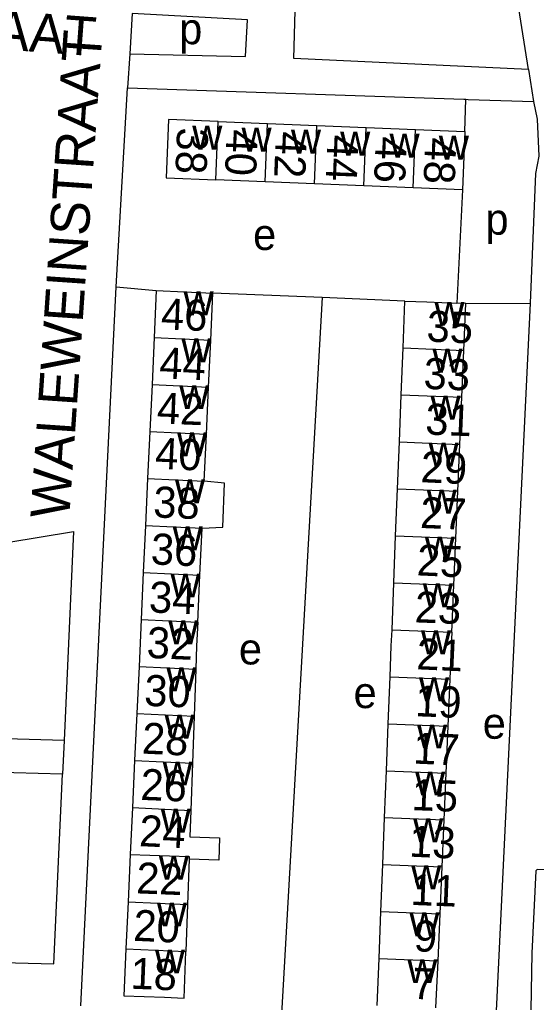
# Model space of a CAD drawing. Extents: x 159675 to 162108, y 386471 to 388472.
# Drawn here: x 160779.5 to 160845.9, y 386954.2 to 387080.5 of the extents above; entities that cross this region are included whole.
import ezdxf

# ---------------------------------------------------------------- set-up
doc = ezdxf.new("R2010")
doc.units = 0
for name, color, linetype in [('BLT_Basislijn', 7, 'Continuous'), ('BLT_Bebouwing', 7, 'Continuous'), ('BLT_Centroide', 7, 'Continuous'), ('BLT_Huisnummer', 7, 'Continuous'), ('BLT_Huisnummer_ tussenligend', 7, 'Continuous'), ('BLT_Onderverdeling_panden', 7, 'Continuous'), ('BLT_Straatnaam', 7, 'Continuous')]:
    doc.layers.add(name, color=color, linetype=linetype)

msp = doc.modelspace()

# ---------------------------------------------------------------- linework, layer by layer
at = {"layer": 'BLT_Basislijn'}
for p, q in [((160793.9, 387081.23), (160793.62, 387076.05)), ((160793.62, 387076.05), (160793.32, 387071.69)), ((160844.85, 387074.04), (160845.51, 387069.92)), ((160791.86, 387046.11), (160793.32, 387071.69)), ((160793.32, 387071.69), (160836.55, 387070.22)), ((160836.55, 387070.22), (160836.82, 387070.22)), ((160836.67, 387066.1), (160836.82, 387070.22)), ((160836.37, 387058.61), (160835.66, 387044.02)), ((160787.31, 386953.76), (160791.86, 387046.11)), ((160791.86, 387046.11), (160797.02, 387045.67)), ((160818.35, 387044.74), (160804.3, 387045.33)), ((160818.35, 387044.74), (160813.1, 386952.69)), ((160828.98, 387044.3), (160818.35, 387044.74)), ((160836.79, 387043.97), (160845.06, 387044.05)), ((160845.06, 387044.05), (160839.85, 386934.69)), ((160785.2, 386987.85), (160784.97, 386983.53))]:
    msp.add_line(p, q, dxfattribs=at)
for points in [[(160844.85, 387074.04), (160814.71, 387075.45), (160815.38, 387100), (160815.63, 387108.74)], [(160844.85, 387074.04), (160840.74, 387100), (160839.47, 387108.01)], [(160793.62, 387076.05), (160808.47, 387075.74), (160808.76, 387080.42), (160793.9, 387081.23)], [(160836.82, 387070.22), (160837.1, 387070.21), (160845.51, 387069.92)], [(160845.51, 387069.92), (160845.99, 387067.68), (160846.21, 387062.9)], [(160846.21, 387062.9), (160845.78, 387060.7), (160845.06, 387044.05)], [(160735.6, 386960.39), (160728.94, 387001.16), (160729.22, 387003.9), (160731.01, 387005.56), (160786.36, 387014.7), (160785.2, 386987.85)], [(160785.2, 386987.85), (160776.15, 386988.09), (160775.89, 386988.32), (160775.92, 386995.02), (160753.34, 386995.77), (160751.93, 386960.01)], [(160784.97, 386983.53), (160756.75, 386984.3), (160755.83, 386959.87)], [(160755.83, 386959.87), (160783.87, 386959.13), (160784.97, 386983.53)], [(160860.44, 386970.92), (160845.97, 386971.28), (160845.81, 386971.07), (160845.29, 386960.51), (160845.09, 386948.32), (160864.77, 386916.45), (160865.08, 386915.53)]]:
    msp.add_lwpolyline(points, dxfattribs=at)
at = {"layer": 'BLT_Bebouwing'}
for p, q in [((160804.96, 387067.37), (160811.3, 387067.11)), ((160811.3, 387067.11), (160817.64, 387066.86)), ((160817.64, 387066.86), (160823.99, 387066.61)), ((160823.99, 387066.61), (160830.33, 387066.35)), ((160830.33, 387066.35), (160836.67, 387066.1)), ((160836.67, 387066.1), (160836.37, 387058.61)), ((160811, 387059.62), (160804.66, 387059.87)), ((160817.34, 387059.37), (160811, 387059.62)), ((160823.69, 387059.11), (160817.34, 387059.37)), ((160830.03, 387058.86), (160823.69, 387059.11)), ((160836.37, 387058.61), (160830.03, 387058.86)), ((160797.02, 387045.67), (160796.74, 387039.63)), ((160797.02, 387045.67), (160804.3, 387045.33)), ((160804.02, 387039.29), (160804.3, 387045.33)), ((160828.74, 387038.27), (160828.98, 387044.3)), ((160836.79, 387043.97), (160835.66, 387044.02)), ((160836.54, 387037.96), (160836.79, 387043.97)), ((160796.74, 387039.63), (160796.47, 387033.59)), ((160803.74, 387033.25), (160804.02, 387039.29)), ((160828.51, 387032.23), (160828.74, 387038.27)), ((160836.28, 387031.93), (160836.54, 387037.96)), ((160796.47, 387033.59), (160796.19, 387027.55)), ((160803.46, 387027.21), (160803.74, 387033.25)), ((160828.27, 387026.2), (160828.51, 387032.23)), ((160836.03, 387025.89), (160836.28, 387031.93)), ((160796.19, 387027.55), (160795.91, 387021.5)), ((160803.18, 387021.17), (160803.46, 387027.21)), ((160828.03, 387020.16), (160828.27, 387026.2)), ((160835.77, 387019.86), (160836.03, 387025.89)), ((160795.91, 387021.5), (160795.63, 387015.46)), ((160827.79, 387014.13), (160828.03, 387020.16)), ((160835.52, 387013.83), (160835.77, 387019.86)), ((160795.63, 387015.46), (160795.35, 387009.42)), ((160802.62, 387009.08), (160802.9, 387015.13)), ((160827.55, 387008.1), (160827.79, 387014.13)), ((160835.26, 387007.79), (160835.52, 387013.83)), ((160795.35, 387009.42), (160795.07, 387003.38)), ((160802.34, 387003.04), (160802.62, 387009.08)), ((160827.32, 387002.06), (160827.55, 387008.1)), ((160835.01, 387001.76), (160835.26, 387007.79)), ((160795.07, 387003.38), (160794.8, 386997.34)), ((160794.8, 386997.34), (160794.52, 386991.29)), ((160802.1, 386997), (160801.88, 386990.95)), ((160826.84, 386989.99), (160827.08, 386996.03)), ((160834.75, 386995.73), (160834.49, 386989.69)), ((160794.52, 386991.29), (160794.24, 386985.25)), ((160801.88, 386990.95), (160801.67, 386984.91)), ((160826.6, 386983.96), (160826.84, 386989.99)), ((160834.49, 386989.69), (160834.23, 386983.66)), ((160794.24, 386985.25), (160793.96, 386979.21)), ((160801.67, 386984.91), (160801.46, 386978.86)), ((160826.36, 386977.93), (160826.6, 386983.96)), ((160834.23, 386983.66), (160833.97, 386977.63)), ((160793.96, 386979.21), (160793.68, 386973.17)), ((160826.12, 386971.89), (160826.36, 386977.93)), ((160833.97, 386977.63), (160833.71, 386971.59)), ((160793.68, 386973.17), (160793.4, 386967.12)), ((160801.23, 386972.61), (160801.03, 386966.77)), ((160825.89, 386965.86), (160826.12, 386971.89)), ((160833.71, 386971.59), (160833.45, 386965.56)), ((160793.4, 386967.12), (160793.12, 386961.08)), ((160801.03, 386966.77), (160800.82, 386960.73)), ((160825.65, 386959.82), (160825.89, 386965.86)), ((160833.45, 386965.56), (160833.19, 386959.53)), ((160825.41, 386953.79), (160825.65, 386959.82)), ((160833.19, 386959.53), (160832.93, 386953.49))]:
    msp.add_line(p, q, dxfattribs=at)
for points in [[(160804.96, 387067.37), (160798.61, 387067.62), (160798.31, 387060.12), (160804.66, 387059.87)], [(160828.98, 387044.3), (160831.79, 387044.18), (160835.66, 387044.02)], [(160802.9, 387015.13), (160805.58, 387015.25), (160805.81, 387020.91), (160803.18, 387021.17)], [(160802.34, 387003.04), (160802.2, 387000), (160802.1, 386997)], [(160827.08, 386996.03), (160827.23, 387000), (160827.32, 387002.06)], [(160835.01, 387001.76), (160834.93, 387000), (160834.75, 386995.73)], [(160801.46, 386978.86), (160801.34, 386975.48), (160805.16, 386975.35), (160805.06, 386972.47), (160801.23, 386972.61)], [(160793.12, 386961.08), (160792.84, 386955.04), (160798.06, 386954.84), (160800.6, 386954.73), (160800.82, 386960.73)]]:
    msp.add_lwpolyline(points, dxfattribs=at)
at = {"layer": 'BLT_Onderverdeling_panden'}
for p, q in [((160804.66, 387059.87), (160804.96, 387067.37)), ((160811, 387059.62), (160811.3, 387067.11)), ((160817.34, 387059.37), (160817.64, 387066.86)), ((160823.69, 387059.11), (160823.99, 387066.61)), ((160830.03, 387058.86), (160830.33, 387066.35)), ((160796.74, 387039.63), (160804.02, 387039.29)), ((160828.74, 387038.27), (160836.54, 387037.96)), ((160796.47, 387033.59), (160803.74, 387033.25)), ((160828.51, 387032.23), (160836.28, 387031.93)), ((160796.19, 387027.55), (160803.46, 387027.21)), ((160828.27, 387026.2), (160836.03, 387025.89)), ((160795.91, 387021.5), (160803.18, 387021.17)), ((160828.03, 387020.16), (160835.77, 387019.86)), ((160795.63, 387015.46), (160802.9, 387015.13)), ((160827.79, 387014.13), (160835.52, 387013.83)), ((160795.35, 387009.42), (160802.62, 387009.08)), ((160827.55, 387008.1), (160835.26, 387007.79)), ((160795.07, 387003.38), (160802.34, 387003.04)), ((160827.32, 387002.06), (160835.01, 387001.76)), ((160794.8, 386997.34), (160802.1, 386997)), ((160827.08, 386996.03), (160834.75, 386995.73)), ((160794.52, 386991.29), (160801.88, 386990.95)), ((160826.84, 386989.99), (160834.49, 386989.69)), ((160794.24, 386985.25), (160801.67, 386984.91)), ((160826.6, 386983.96), (160834.23, 386983.66)), ((160793.96, 386979.21), (160801.46, 386978.86)), ((160826.36, 386977.93), (160833.97, 386977.63)), ((160826.12, 386971.89), (160833.71, 386971.59)), ((160793.4, 386967.12), (160801.03, 386966.77)), ((160825.89, 386965.86), (160833.45, 386965.56)), ((160793.12, 386961.08), (160800.82, 386960.73)), ((160825.65, 386959.82), (160833.19, 386959.53))]:
    msp.add_line(p, q, dxfattribs=at)
msp.add_lwpolyline([(160793.68, 386973.17), (160801.25, 386972.94), (160801.23, 386972.61)], dxfattribs=at)

# ---------------------------------------------------------------- texts
at = {"layer": 'BLT_Centroide'}
for s, p in [('p', (160799.96, 387077.3)), ('w', (160801.64, 387063.75)), ('w', (160807.98, 387063.5)), ('w', (160814.33, 387063.25)), ('w', (160820.66, 387062.98)), ('w', (160827, 387062.73)), ('w', (160833.34, 387062.47)), ('p', (160839.33, 387052.83)), ('e', (160809.46, 387050.86)), ('w', (160800.52, 387042.47)), ('w', (160832.77, 387041.12)), ('w', (160800.24, 387036.44)), ('w', (160832.52, 387035.09)), ('w', (160799.96, 387030.41)), ('w', (160832.27, 387029.06)), ('w', (160799.69, 387024.34)), ('w', (160832.02, 387023.03)), ('w', (160799.41, 387018.31)), ('w', (160831.78, 387017)), ('w', (160799.12, 387012.28)), ('w', (160831.53, 387010.97)), ('w', (160798.84, 387006.22)), ('w', (160831.28, 387004.94)), ('w', (160798.56, 387000.19)), ('w', (160831.04, 386998.91)), ('e', (160807.64, 386997.61)), ('w', (160798.32, 386994.16)), ('e', (160822.38, 386992)), ('w', (160830.79, 386992.88)), ('e', (160838.98, 386988.06)), ('w', (160798.08, 386988.09)), ('w', (160830.54, 386986.81)), ('w', (160797.83, 386982.06)), ('w', (160830.29, 386980.78)), ('w', (160797.59, 386976)), ('w', (160830.04, 386974.75)), ('w', (160797.34, 386969.97)), ('w', (160829.79, 386968.72)), ('w', (160797.09, 386963.94)), ('w', (160829.55, 386962.69)), ('w', (160796.84, 386957.91)), ('w', (160829.29, 386956.66))]:
    msp.add_text(s, height=4, dxfattribs=at).set_placement(p)
at = {"layer": 'BLT_Huisnummer'}
for s, rotation, p in [('38', 267.7155, (160799.71, 387066.64)), ('42', 267.7155, (160812.4, 387066.14)), ('48', 267.7155, (160831.61, 387065.36)), ('46', 357.7256, (160797.57, 387040.67)), ('35', 357.426, (160831.71, 387039.11)), ('42', 357.7256, (160797.05, 387028.58)), ('29', 357.426, (160830.94, 387021.03)), ('38', 357.7256, (160796.58, 387016.51)), ('25', 357.426, (160830.45, 387009.06)), ('34', 357.7256, (160796.03, 387004.3)), ('21', 357.426, (160830.41, 386996.99)), ('30', 357.7256, (160795.42, 386992.3)), ('17', 357.426, (160829.98, 386984.88)), ('26', 357.7256, (160794.93, 386980.21)), ('13', 357.426, (160829.46, 386972.92)), ('22', 357.7256, (160794.39, 386968.2)), ('9', 357.426, (160830.06, 386960.77)), ('18', 357.7256, (160793.66, 386955.95))]:
    msp.add_text(s, height=4, rotation=rotation, dxfattribs=at).set_placement(p)
at = {"layer": 'BLT_Huisnummer_ tussenligend'}
for s, rotation, p in [('40', 267.7155, (160806.08, 387066.41)), ('44', 267.7155, (160819.04, 387065.72)), ('46', 267.7155, (160825.24, 387065.49)), ('44', 357.3619, (160797.35, 387034.39)), ('33', 357.7385, (160831.33, 387033.03)), ('31', 357.7385, (160831.55, 387027.16)), ('40', 357.3619, (160796.81, 387022.78)), ('27', 357.7385, (160830.88, 387015.15)), ('36', 357.3619, (160796.26, 387010.48)), ('23', 357.7385, (160830.19, 387003.02)), ('32', 357.3619, (160795.73, 386998.46)), ('19', 357.7385, (160830.24, 386990.96)), ('28', 357.3619, (160795.11, 386986.16)), ('15', 357.7385, (160829.79, 386978.9)), ('24', 357.3619, (160794.76, 386974.27)), ('11', 357.7385, (160829.66, 386966.72)), ('20', 357.3619, (160794.01, 386962.11)), ('7', 357.7385, (160829.84, 386954.65))]:
    msp.add_text(s, height=4, rotation=rotation, dxfattribs=at).set_placement(p)
at = {"layer": 'BLT_Straatnaam'}
for s, rotation, p in [('MORIAENSTRAAT', 355.734, (160731.67, 387080.03)), ('WALEWEINSTRAAT', 86.077, (160785.82, 387016.26))]:
    msp.add_text(s, height=5, rotation=rotation, dxfattribs=at).set_placement(p)

doc.saveas('drawing.dxf')
